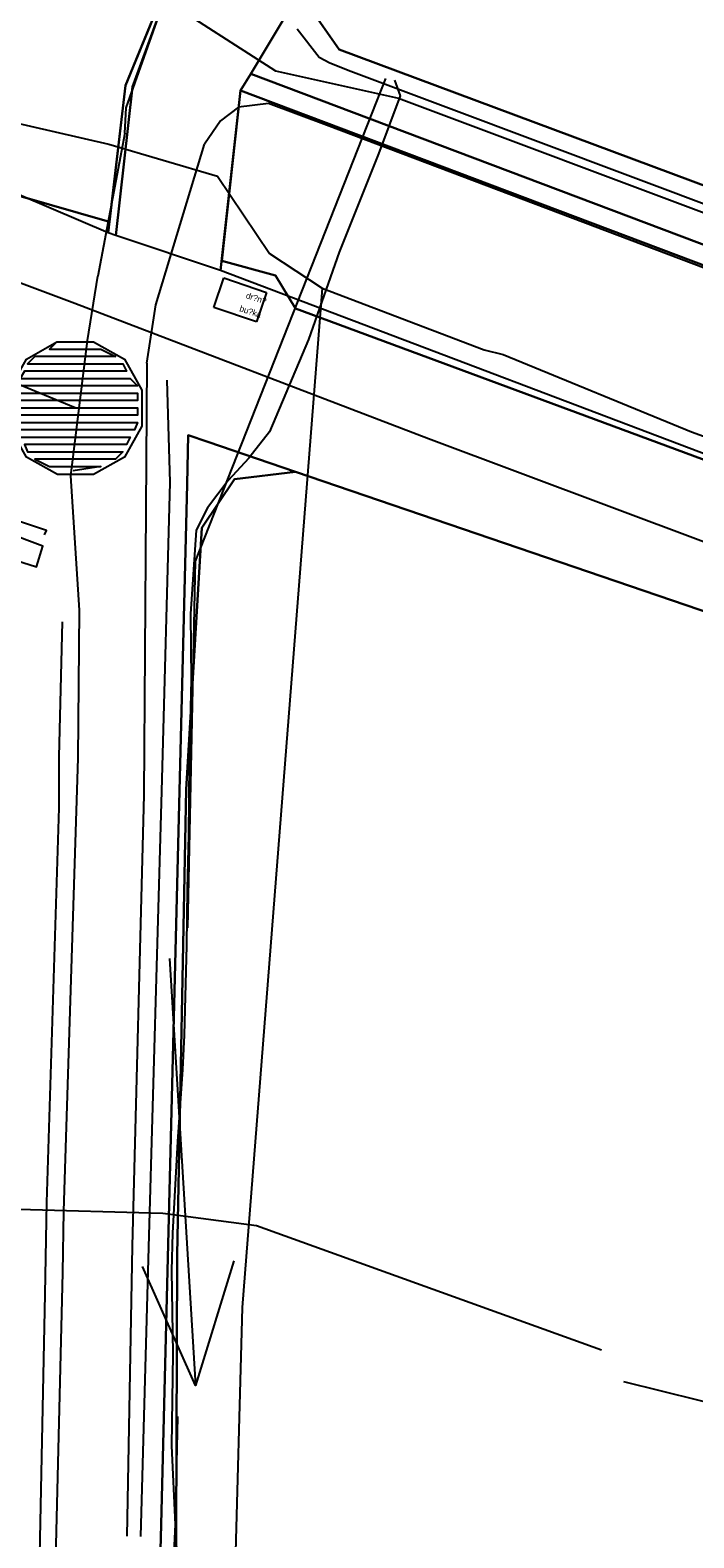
# Model space of a CAD drawing. Extents: x -645676 to -642474, y -1077513 to -1072613.
# Drawn here: x -644570.9 to -644516.6, y -1074990.7 to -1074867.3 of the extents above; entities that cross this region are included whole.
import ezdxf

# ---------------------------------------------------------------- set-up
doc = ezdxf.new("R2010")
doc.units = 0
for name, color, linetype in [('_elezni_n__tra_', 7, 'Continuous'), ('KN', 7, 'Continuous'), ('KULTURY_STAV', 7, 'Continuous'), ('Obvod_KP_', 7, 'Continuous'), ('OBVOD_PU', 7, 'Continuous'), ('P__kop___st_vaj_c_', 7, 'Continuous'), ('PC_NAVRH', 7, 'Continuous'), ('PC_STAN_NAVRH', 7, 'Continuous'), ('PLYNOVOD', 7, 'Continuous'), ('SDELOVACI', 7, 'Continuous'), ('Silnice_II__t__dy_a_III__t__dy', 7, 'Continuous'), ('VODOVOD', 7, 'Continuous')]:
    doc.layers.add(name, color=color, linetype=linetype)

# ---------------------------------------------------------------- blocks, each defined once
blk = doc.blocks.new('$406')
blk.add_lwpolyline([(-0.19, 0.72), (0.2, 0.72), (0.54, 0.53), (0.73, 0.19), (0.73, -0.2), (0.54, -0.54), (0.2, -0.73), (-0.19, -0.73), (-0.53, -0.54), (-0.72, -0.2), (-0.72, 0.19), (-0.53, 0.53), (-0.2, 0.72), (-0.28, 0.64), (0.28, 0.64), (0.44, 0.56), (-0.44, 0.56), (-0.52, 0.48), (0.52, 0.48), (0.56, 0.4), (-0.55, 0.4), (-0.6, 0.32), (0.6, 0.32), (0.68, 0.24), (-0.59, 0.24), (-0.65, 0.24), (-0.68, 0.16), (0.59, 0.16), (0.68, 0.16), (0.68, 0.08), (-0.59, 0.08), (-0.68, 0.08), (-0.68, 0), (0.59, 0), (0.68, 0), (0.68, -0.08), (-0.59, -0.08), (-0.68, -0.08), (-0.68, -0.16), (0.59, -0.16), (0.68, -0.16), (0.65, -0.24), (-0.62, -0.24), (-0.65, -0.24), (-0.6, -0.32), (0.6, -0.32), (0.56, -0.4), (-0.55, -0.4), (-0.52, -0.48), (0.52, -0.48), (0.44, -0.56), (-0.44, -0.56), (-0.28, -0.64), (0.28, -0.64), (-0.02, -0.69)])
blk = doc.blocks.new('6$1520')
blk.add_line((-3.5, 0), (3.5, 0))
blk.add_lwpolyline([(1.5, 0.75), (3.5, 0), (1.5, -0.75)])
blk = doc.blocks.new('6$3520')
for p, q in [((-0.76, 0), (-0.76, -1)), ((0, -1), (0, 0)), ((0.76, 0), (0.76, -1))]:
    blk.add_line(p, q)
blk.add_lwpolyline([(-3.5, 0), (-2.23, 0), (-1.48, 0), (-1.48, -1), (-0.21, -1), (1.06, -1), (1.5, -1), (1.5, 0), (2.77, 0), (3.5, 0)])

msp = doc.modelspace()

# ---------------------------------------------------------------- linework, layer by layer
at = {"layer": '_elezni_n__tra_'}
for p, q in [((-644555.84, -1074890.03), (-644555.01, -1074887.61)), ((-644555.01, -1074887.61), (-644551.52, -1074888.81)), ((-644551.52, -1074888.81), (-644552.35, -1074891.21)), ((-644552.35, -1074891.21), (-644555.84, -1074890.03))]:
    msp.add_line(p, q, dxfattribs=at)
msp.add_lwpolyline([(-645032.05, -1074719.88), (-645007.73, -1074729.17), (-644983.14, -1074736.55), (-644942.37, -1074750.02), (-644914.47, -1074760.84), (-644882.89, -1074772.03), (-644837.1, -1074789.71), (-644791.46, -1074806.27), (-644722.98, -1074831.82), (-644692.05, -1074843.35), (-644645.1, -1074860.33), (-644595.62, -1074879.05), (-644567.2, -1074889.68), (-644538.28, -1074900.75), (-644463.04, -1074928.93), (-644414.14, -1074947.15), (-644324.54, -1074980.78), (-644238.86, -1075012.25), (-644147.17, -1075045.91), (-644073.62, -1075073.69), (-644009.64, -1075097.37)], dxfattribs=at)
at = {"layer": 'KN'}
for points in [[(-644637.95, -1074800.11), (-644558.41, -1074855.87), (-644556.46, -1074857.72), (-644559.79, -1074863.86), (-644563.05, -1074871.86), (-644564.49, -1074883.93), (-644583.74, -1074875.71)], [(-644560.38, -1074866.24), (-644562.5, -1074871.98), (-644563.85, -1074884.14), (-644564.49, -1074883.93), (-644563.05, -1074871.86), (-644559.79, -1074863.86)], [(-644549.87, -1074866.01), (-644552.8, -1074870.9), (-644553.65, -1074872.28), (-644555.28, -1074886.99), (-644563.85, -1074884.14), (-644562.5, -1074871.98), (-644560.38, -1074866.24)]]:
    msp.add_lwpolyline(points, dxfattribs=at)
for points in [[(-644520.18, -1074860.44), (-644517.92, -1074862.59), (-644515.13, -1074859.66), (-644501.16, -1074873.05), (-644510.39, -1074882.04), (-644545.57, -1074868.92), (-644548.83, -1074864.26), (-644539.77, -1074853.4), (-644526.68, -1074866.18)], [(-644510.39, -1074882.04), (-644486.62, -1074890.85), (-644475.06, -1074895.14), (-644451.2, -1074903.97), (-644436.08, -1074909.55), (-644426.98, -1074912.91), (-644402.85, -1074921.87), (-644379.47, -1074930.51), (-644366.6, -1074935.27), (-644355.77, -1074939.27), (-644357.45, -1074943.99), (-644454.44, -1074908.02), (-644552.8, -1074870.9), (-644549.87, -1074866.01), (-644548.83, -1074864.26), (-644545.57, -1074868.92)], [(-644454.44, -1074908.02), (-644455.03, -1074909.51), (-644553.65, -1074872.28), (-644552.8, -1074870.9)], [(-644455.03, -1074909.51), (-644460.31, -1074923.02), (-644555.28, -1074886.99), (-644553.65, -1074872.28)]]:
    msp.add_lwpolyline(points, close=True, dxfattribs=at)
at = {"layer": 'KULTURY_STAV'}
for points in [[(-644638.36, -1074799.82), (-644558.41, -1074855.87), (-644552.95, -1074850.62), (-644551.14, -1074852.54), (-644556.46, -1074857.72), (-644559.79, -1074863.86), (-644563.05, -1074871.86), (-644564.38, -1074883.03), (-644584.34, -1074877.29)], [(-644584.34, -1074877.29), (-644564.38, -1074883.03), (-644564.3, -1074882.39), (-644563.05, -1074871.86), (-644559.95, -1074864.26)], [(-644426.98, -1074912.91), (-644436.08, -1074909.55), (-644431.41, -1074897.15), (-644440.86, -1074893.59), (-644439.06, -1074888.82), (-644442.1, -1074887.67), (-644444.85, -1074886.63), (-644443.6, -1074883.01), (-644466.19, -1074870.46), (-644467.57, -1074874.46), (-644470.19, -1074881.81), (-644475.06, -1074895.14), (-644486.62, -1074890.85), (-644485.07, -1074886.79), (-644481.75, -1074878.32), (-644485.4, -1074876.89), (-644484.82, -1074875.25), (-644483.57, -1074872.74), (-644482.14, -1074869.88), (-644492.62, -1074864.66), (-644501.16, -1074873.05), (-644510.39, -1074882.04), (-644545.57, -1074868.92), (-644548.83, -1074864.26)], [(-644548.83, -1074864.26), (-644545.57, -1074868.92), (-644510.39, -1074882.04), (-644486.62, -1074890.85), (-644475.06, -1074895.14), (-644451.2, -1074903.97), (-644436.08, -1074909.55), (-644426.98, -1074912.91), (-644402.85, -1074921.87), (-644379.47, -1074930.51), (-644366.6, -1074935.27), (-644355.77, -1074939.27), (-644341.9, -1074944.49), (-644337.02, -1074946.32), (-644333.03, -1074947.83), (-644318.2, -1074953.42), (-644286.02, -1074973.12)], [(-644555.19, -1074886.21), (-644550.78, -1074887.41), (-644549.15, -1074890.12), (-644460.31, -1074923.02), (-644458.3, -1074923.78), (-644434.2, -1074932.86), (-644410.38, -1074941.83), (-644386.94, -1074950.66), (-644363.17, -1074959.61), (-644343, -1074967.15), (-644322.8, -1074974.71), (-644319.77, -1074960.67), (-644319.57, -1074959.78), (-644338.82, -1074952.58), (-644357.97, -1074945.41), (-644381.97, -1074936.53), (-644405.23, -1074927.93), (-644429.28, -1074919.03), (-644453.48, -1074910.08), (-644455.03, -1074909.51), (-644553.65, -1074872.28), (-644555.19, -1074886.21)], [(-644553.65, -1074872.28), (-644455.03, -1074909.51), (-644453.48, -1074910.08), (-644429.28, -1074919.03), (-644405.23, -1074927.93), (-644381.97, -1074936.53), (-644357.97, -1074945.41), (-644338.82, -1074952.58), (-644319.57, -1074959.78), (-644319.77, -1074960.67), (-644322.8, -1074974.71), (-644343, -1074967.15), (-644363.17, -1074959.61), (-644386.94, -1074950.66), (-644410.38, -1074941.83), (-644434.2, -1074932.86), (-644458.3, -1074923.78), (-644460.31, -1074923.02), (-644549.15, -1074890.12), (-644550.78, -1074887.41), (-644555.19, -1074886.21), (-644553.65, -1074872.28)], [(-644570.53, -1075092.51), (-644563.77, -1075059.63), (-644561.36, -1075031.63), (-644560.18, -1074990.72), (-644558.03, -1074904.5), (-644557.93, -1074900.48)], [(-644127.45, -1075086.98), (-644129.42, -1075059.78), (-644147.15, -1075053.4), (-644187.28, -1075037.16), (-644343.27, -1074978.43), (-644510.38, -1074916.7), (-644549.16, -1074903.47), (-644556.33, -1074901.02), (-644557.93, -1074900.48), (-644558.03, -1074904.5), (-644560.18, -1074990.72), (-644561.36, -1075031.63), (-644563.77, -1075059.63), (-644570.53, -1075092.51)], [(-644557.93, -1074900.48), (-644556.33, -1074901.02), (-644549.16, -1074903.47), (-644554.14, -1074904.08), (-644556.81, -1074908.05), (-644558.1, -1074929.47), (-644558.84, -1074967.55), (-644558.93, -1074990.26), (-644558.6, -1075017.51), (-644560.06, -1075051.56), (-644563.36, -1075067.72), (-644569.63, -1075092.35)], [(-644569.63, -1075092.35), (-644563.36, -1075067.72), (-644560.06, -1075051.56), (-644558.6, -1075017.51), (-644558.93, -1074990.26), (-644558.84, -1074967.55), (-644558.1, -1074929.47), (-644556.81, -1074908.05), (-644554.14, -1074904.08), (-644549.16, -1074903.47)], [(-644549.16, -1074903.47), (-644510.38, -1074916.7), (-644343.27, -1074978.43), (-644187.28, -1075037.16), (-644147.15, -1075053.4), (-644150.84, -1075051.91), (-644150.35, -1075080.54), (-644148.65, -1075103.5)]]:
    msp.add_lwpolyline(points, dxfattribs=at)
at = {"layer": 'Obvod_KP_'}
msp.add_lwpolyline([(-644288.4, -1074987.6), (-644322.8, -1074974.71), (-644343, -1074967.15), (-644363.17, -1074959.61), (-644386.94, -1074950.66), (-644410.38, -1074941.83), (-644434.2, -1074932.86), (-644458.3, -1074923.78), (-644460.31, -1074923.02), (-644555.28, -1074886.99), (-644563.85, -1074884.14), (-644564.49, -1074883.93), (-644583.74, -1074875.71)], dxfattribs=at)
at = {"layer": 'OBVOD_PU'}
msp.add_lwpolyline([(-644288.4, -1074987.6), (-644322.8, -1074974.71), (-644343, -1074967.15), (-644363.17, -1074959.61), (-644386.94, -1074950.66), (-644410.38, -1074941.83), (-644434.2, -1074932.86), (-644458.3, -1074923.78), (-644460.31, -1074923.02), (-644555.28, -1074886.99), (-644563.85, -1074884.14), (-644564.49, -1074883.93), (-644583.74, -1074875.71)], dxfattribs=at)
at = {"layer": 'P__kop___st_vaj_c_'}
for points in [[(-644561.8, -1074990.59), (-644561.15, -1074966.93), (-644560.1, -1074929.6), (-644559.41, -1074904.35), (-644559.64, -1074895.97)], [(-644568.25, -1074915.76), (-644568.53, -1074926.8), (-644568.53, -1074930.97), (-644569.54, -1074963.28), (-644569.66, -1074970.78), (-644570.35, -1075004.08), (-644570.6, -1075012.03), (-644571.46, -1075030.88), (-644571.62, -1075038.82)]]:
    msp.add_lwpolyline(points, dxfattribs=at)
at = {"layer": 'PC_NAVRH'}
msp.add_lwpolyline([(-644567.19, -1074898.23), (-644579.49, -1074893.18), (-644609.51, -1074881.01), (-644677.32, -1074855.63), (-644745, -1074831.03), (-644754.83, -1074829.35), (-644791.71, -1074816.01), (-644820.96, -1074805.79), (-644875.57, -1074788.7), (-644932.63, -1074770.57), (-645017.52, -1074743.9), (-645048.97, -1074734.32), (-645061.39, -1074728.88), (-645092.58, -1074713.99), (-645134.64, -1074690.69), (-645139.68, -1074688.36), (-645154.82, -1074684.34), (-645162.37, -1074683.15), (-645179.59, -1074665.73)], dxfattribs=at)
at = {"layer": 'PLYNOVOD'}
for p, q in [((-644560.43, -1074864.47), (-644550.79, -1074870.66)), ((-644550.79, -1074870.66), (-644540.72, -1074872.91)), ((-644540.72, -1074872.91), (-644506.56, -1074885.71))]:
    msp.add_line(p, q, dxfattribs=at)
for points in [[(-644569.7, -1074908.64), (-644569.52, -1074908.29), (-644571.74, -1074907.54)], [(-644572.49, -1074910.56), (-644570.34, -1074911.26), (-644569.84, -1074909.57), (-644572.8, -1074908.45)], [(-644673.81, -1074947.43), (-644635.1, -1074962.07), (-644585.11, -1074963.45), (-644571.92, -1074963.81), (-644571.81, -1074963.81), (-644560.02, -1074964.14), (-644552.34, -1074965.15), (-644524.12, -1074975.33)]]:
    msp.add_lwpolyline(points, dxfattribs=at)
at = {"layer": 'SDELOVACI'}
for points in [[(-644541.06, -1074871.43), (-644540.58, -1074872.72), (-644542.35, -1074877.46), (-644545.58, -1074885.51), (-644548.1, -1074892.64), (-644551.27, -1074900.21), (-644552.98, -1074902.36), (-644554.65, -1074904.18), (-644556.34, -1074906.43)], [(-644577.64, -1074873.63), (-644564.43, -1074876.66), (-644555.54, -1074879.29), (-644551.29, -1074885.62), (-644546.98, -1074888.45)], [(-644546.98, -1074888.45), (-644553.52, -1074971.86), (-644554.13, -1074994.89), (-644555.29, -1075039.09), (-644556.43, -1075050.48), (-644557.99, -1075062.09), (-644560.38, -1075075.22), (-644564.89, -1075096.59)], [(-644546.98, -1074888.45), (-644533.71, -1074893.5), (-644532.16, -1074893.87), (-644516.74, -1074900.2), (-644484.62, -1074911.88), (-644449.65, -1074924.45), (-644433.01, -1074931.12), (-644418.48, -1074937.53), (-644379.32, -1074951.76), (-644346.01, -1074963.84), (-644321.09, -1074973.09)], [(-644546.98, -1074888.45), (-644533.71, -1074893.5), (-644532.16, -1074893.87), (-644516.74, -1074900.2), (-644484.62, -1074911.88), (-644449.65, -1074924.45), (-644433.01, -1074931.12), (-644418.48, -1074937.53), (-644379.32, -1074951.76), (-644346.01, -1074963.84), (-644321.09, -1074973.09)], [(-644546.98, -1074888.45), (-644533.71, -1074893.5), (-644532.16, -1074893.87), (-644516.74, -1074900.2), (-644484.62, -1074911.88), (-644449.65, -1074924.45), (-644433.01, -1074931.12), (-644418.48, -1074937.53), (-644379.32, -1074951.76), (-644346.01, -1074963.84), (-644321.09, -1074973.09)], [(-644556.34, -1074906.43), (-644557.28, -1074908.24), (-644557.74, -1074915.1), (-644557.69, -1074920.5), (-644557.85, -1074927.27), (-644557.9, -1074933.2), (-644558.03, -1074937.6), (-644558.08, -1074942.25), (-644558.25, -1074949.58), (-644558.39, -1074952.38), (-644558.81, -1074958.28), (-644559.21, -1074965.78), (-644559.31, -1074968.82), (-644559.18, -1074975.65), (-644559.31, -1074983.19), (-644558.99, -1074989.62), (-644559.44, -1074998.87), (-644559.82, -1075005.92), (-644560.23, -1075012.36), (-644563.33, -1075012.38), (-644569.77, -1075012.35), (-644571.5, -1075012.42)], [(-644556.34, -1074906.43), (-644557.28, -1074908.24), (-644557.74, -1074915.1), (-644557.69, -1074920.5), (-644557.85, -1074927.27), (-644557.9, -1074933.2), (-644558.03, -1074937.6), (-644558.08, -1074942.25), (-644558.25, -1074949.58), (-644558.39, -1074952.38), (-644558.81, -1074958.28), (-644559.21, -1074965.78), (-644559.31, -1074968.82), (-644559.18, -1074975.65), (-644559.31, -1074983.19), (-644558.99, -1074989.62), (-644559.44, -1074998.87), (-644559.82, -1075005.92), (-644560.23, -1075012.36), (-644563.33, -1075012.38), (-644569.77, -1075012.35), (-644571.5, -1075012.42)]]:
    msp.add_lwpolyline(points, dxfattribs=at)
at = {"layer": 'Silnice_II__t__dy_a_III__t__dy'}
for p, q in [((-644563.01, -1074873.7), (-644559.55, -1074863.97)), ((-644549.02, -1074867.24), (-644547.21, -1074869.54)), ((-644547.21, -1074869.54), (-644546.33, -1074870)), ((-644546.33, -1074870), (-644544.63, -1074870.69)), ((-644544.63, -1074870.69), (-644511.17, -1074883.25)), ((-644563.11, -1074875.77), (-644563.01, -1074873.7)), ((-644553.81, -1074873.63), (-644555.3, -1074874.75)), ((-644551.37, -1074873.33), (-644553.81, -1074873.63)), ((-644546.4, -1074875.18), (-644551.37, -1074873.33)), ((-644555.3, -1074874.75), (-644556.59, -1074876.66)), ((-644563.11, -1074875.77), (-644565.34, -1074887.47)), ((-644513.14, -1074887.77), (-644546.4, -1074875.18)), ((-644560.59, -1074889.8), (-644556.59, -1074876.66)), ((-644566.17, -1074892.72), (-644565.34, -1074887.47)), ((-644561.32, -1074894.58), (-644560.59, -1074889.8)), ((-644567.54, -1074903.81), (-644566.17, -1074892.72)), ((-644561.32, -1074894.58), (-644561.41, -1074906.57)), ((-644566.82, -1074914.79), (-644567.54, -1074903.81)), ((-644561.41, -1074906.57), (-644561.57, -1074929.91)), ((-644566.94, -1074926.92), (-644566.82, -1074914.79)), ((-644568.1, -1074963.97), (-644566.94, -1074926.92)), ((-644561.57, -1074929.91), (-644562.53, -1074966.83)), ((-644568.18, -1074969.01), (-644568.1, -1074963.97)), ((-644562.53, -1074966.83), (-644562.96, -1074990.56)), ((-644569.06, -1075004.15), (-644568.18, -1074969.01))]:
    msp.add_line(p, q, dxfattribs=at)
at = {"layer": 'VODOVOD'}
for p, q in [((-644541.8, -1074871.3), (-644557.36, -1074910.79)), ((-644557.36, -1074910.79), (-644557.98, -1074940.78)), ((-644558.81, -1074980.77), (-644559.53, -1075015.38))]:
    msp.add_line(p, q, dxfattribs=at)

# ---------------------------------------------------------------- block references
at = {"layer": 'PC_STAN_NAVRH', "xscale": 7.5, "yscale": 7.5}
msp.add_blockref('$406', (-644567.19, -1074898.23), dxfattribs=at)
at = {"layer": 'PLYNOVOD', "xscale": 5, "yscale": 5.000000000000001, "rotation": -13.901887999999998}
msp.add_blockref('6$3520', (-644505.31, -1074982.12), dxfattribs=at)
at = {"layer": 'VODOVOD', "xscale": 5.000000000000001, "yscale": 5, "rotation": -86.49694499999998}
msp.add_blockref('6$1520', (-644558.4, -1074960.78), dxfattribs=at)

# ---------------------------------------------------------------- texts
at = {"layer": '_elezni_n__tra_'}
for s, p in [('bu?ka', (-644553.78, -1074890.32)), ('dr?n? ', (-644553.25, -1074889.25))]:
    msp.add_text(s, height=0.5, rotation=342.009, dxfattribs=at).set_placement(p)

doc.saveas('drawing.dxf')
